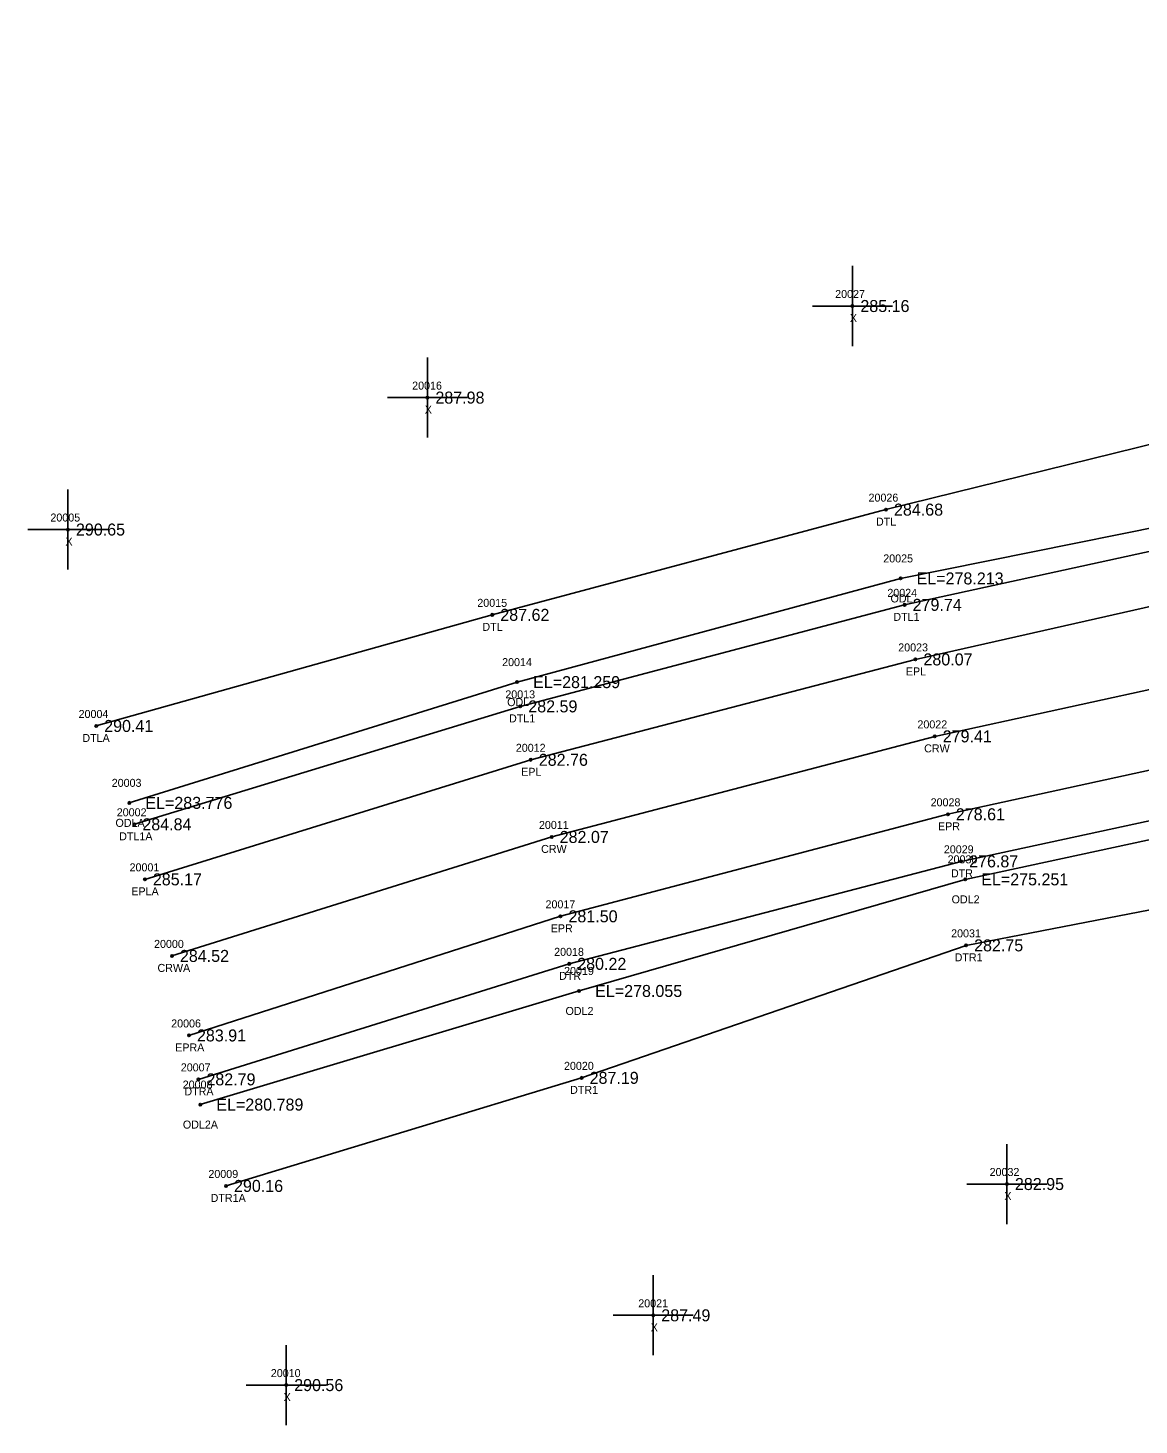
# Model space of a CAD drawing. Extents: x 2275563 to 2277161, y 1075719 to 1076412.
# Drawn here: x 2275563.1 to 2275701.9, y 1075902.3 to 1076077 of the extents above; entities that cross this region are included whole.
import ezdxf

# ---------------------------------------------------------------- set-up
doc = ezdxf.new("R2010")
doc.units = 0
for name, color, linetype in [('RD_DTM_BkLn1', 7, 'Continuous'), ('RD_EX_H2O', 7, 'Continuous'), ('RD_EX_H2O_txCode', 7, 'Continuous'), ('RD_EX_Misc', 7, 'Continuous'), ('RD_EX_Misc_txCode', 7, 'Continuous'), ('RD_EX_Road', 7, 'Continuous'), ('RD_EX_Road_txCode', 7, 'Continuous'), ('RD_EX_TX_H2O_ELEV', 7, 'Continuous'), ('RD_EX_TX_Misc_ELEV', 7, 'Continuous'), ('RD_EX_TX_Road_ELEV', 7, 'Continuous'), ('RD_HC_Survey_ELEV', 7, 'Continuous'), ('RD_HC_Survey_txCode', 7, 'Continuous'), ('RD_SMD_Locator', 7, 'Continuous')]:
    doc.layers.add(name, color=color, linetype=linetype)

msp = doc.modelspace()

# ---------------------------------------------------------------- linework, layer by layer
at = {"layer": 'RD_DTM_BkLn1'}
msp.add_lwpolyline([(2275581.11, 1075960.98), (2275628.56, 1075975.85), (2275676.42, 1075988.42), (2275723.3, 1075998.64), (2275773.11, 1076007.87), (2275820.75, 1076014.85), (2275866.6, 1076020.4), (2275966.91, 1076031.19), (2276055.16, 1076040.4), (2276149.88, 1076050.18), (2276235.38, 1076058.41), (2276319.71, 1076067.21)], dxfattribs=at)
at = {"layer": 'RD_EX_H2O'}
for points in [[(2275571.65, 1075989.72), (2275621.14, 1076003.61), (2275670.33, 1076016.76), (2275718.82, 1076028.73), (2275768.35, 1076037.39), (2275818.36, 1076043.83), (2275863.99, 1076048.58), (2275939.76, 1076056.32), (2275942.53, 1076068.3)], [(2275576.42, 1075977.43), (2275624.64, 1075992.17), (2275672.66, 1076004.86), (2275721.55, 1076015.52), (2275771.33, 1076024.61), (2275820.46, 1076031.17), (2275865.41, 1076036.37), (2275943.27, 1076044.07), (2275943.38, 1076052.27), (2275942.53, 1076068.3)], [(2275575.79, 1075980.11), (2275624.24, 1075995.2), (2275672.15, 1076008.16), (2275721.35, 1076018.05), (2275770.75, 1076027.72), (2275820.07, 1076033.88), (2275865.07, 1076039.19), (2275940.33, 1076048.37)], [(2275584.42, 1075945.55), (2275630.75, 1075959.99), (2275679.72, 1075972.8), (2275727.1, 1075983.01), (2275776.52, 1075992.46), (2275822.09, 1075998.61), (2275868.31, 1076005.5), (2275971.07, 1076013.85), (2276058.03, 1076018.84), (2276110, 1076025.4), (2276114.25, 1076022.31), (2276152.59, 1076021.64), (2276188.46, 1076022.22), (2276200.36, 1076021.35), (2276207.63, 1076015.4), (2276245.53, 1076014.24), (2276263.41, 1076017.81), (2276276.57, 1076007.97), (2276280.95, 1075989.03), (2276329.97, 1075967.39)], [(2275584.66, 1075942.4), (2275631.99, 1075956.6), (2275680.23, 1075970.55), (2275727.34, 1075980.71), (2275776.9, 1075989.93), (2275822.49, 1075996.83), (2275868.2, 1076003.14), (2275971.77, 1076011.3), (2276058.74, 1076015.62), (2276117.31, 1076020.2), (2276152.71, 1076018.31), (2276188.2, 1076020.3), (2276200.59, 1076018.25), (2276207.46, 1076011.88), (2276246.17, 1076010.02), (2276264.15, 1076012.48), (2276274.37, 1076006.56), (2276276.43, 1075986.9), (2276334.04, 1075961.68)], [(2275587.87, 1075932.23), (2275632.3, 1075945.74), (2275680.34, 1075962.3), (2275730.43, 1075971.98), (2275777.84, 1075981.49), (2275823.91, 1075987.34), (2275869.26, 1075992.75), (2275941.88, 1076000), (2275968.29, 1076005.71), (2275973.41, 1076009.09), (2276058.49, 1076013.63), (2276114.54, 1076018.47), (2276125.61, 1076012.99), (2276153.29, 1076014.06), (2276186.69, 1076017.67), (2276196.76, 1076016.05), (2276210.13, 1076008.45), (2276246.2, 1076005.42), (2276264.34, 1076010.6), (2276271.38, 1076006), (2276275.05, 1075983.37), (2276331.39, 1075956.06)]]:
    msp.add_lwpolyline(points, dxfattribs=at)
at = {"layer": 'RD_EX_Misc'}
for p, q in [((2275666.13, 1076037.21), (2275666.13, 1076047.21)), ((2275661.13, 1076042.21), (2275671.13, 1076042.21)), ((2275613.03, 1076025.76), (2275613.03, 1076035.76)), ((2275608.03, 1076030.76), (2275618.03, 1076030.76)), ((2275568.12, 1076009.27), (2275568.12, 1076019.27)), ((2275563.12, 1076014.27), (2275573.12, 1076014.27)), ((2275685.44, 1075927.47), (2275685.44, 1075937.47)), ((2275680.44, 1075932.47), (2275690.44, 1075932.47)), ((2275641.25, 1075911.06), (2275641.25, 1075921.06)), ((2275636.25, 1075916.06), (2275646.25, 1075916.06)), ((2275595.39, 1075902.34), (2275595.39, 1075912.34)), ((2275590.39, 1075907.34), (2275600.39, 1075907.34))]:
    msp.add_line(p, q, dxfattribs=at)
at = {"layer": 'RD_EX_Road'}
for points in [[(2275577.73, 1075970.55), (2275625.95, 1075985.49), (2275674.01, 1075998.04), (2275722.5, 1076008.98), (2275771.65, 1076017.82), (2275820.48, 1076025.1), (2275865.7, 1076030.61), (2275949.17, 1076039.36), (2275965.19, 1076041.07), (2276054.28, 1076050.49), (2276149.42, 1076060.39), (2276235.13, 1076068.68), (2276318.87, 1076076.96)], [(2275583.24, 1075951.04), (2275629.66, 1075965.93), (2275678.06, 1075978.68), (2275725.56, 1075989.06), (2275775.66, 1075998.23), (2275820.79, 1076005.15), (2275867.87, 1076010.76), (2275970.82, 1076021.78), (2276056.64, 1076030.61), (2276150.8, 1076040.39), (2276237.04, 1076048.76), (2276320.71, 1076057.95)]]:
    msp.add_lwpolyline(points, dxfattribs=at)
at = {"layer": 'RD_SMD_Locator'}
for centre in [(2275666.13, 1076042.21), (2275613.03, 1076030.76), (2275670.33, 1076016.76), (2275568.12, 1076014.27), (2275672.15, 1076008.16), (2275672.66, 1076004.86), (2275621.14, 1076003.61), (2275674.01, 1075998.04), (2275624.24, 1075995.2), (2275624.64, 1075992.17), (2275571.65, 1075989.72), (2275676.42, 1075988.42), (2275625.95, 1075985.49), (2275575.79, 1075980.11), (2275678.06, 1075978.68), (2275576.42, 1075977.43), (2275628.56, 1075975.85), (2275679.72, 1075972.8), (2275577.73, 1075970.55), (2275680.23, 1075970.55), (2275629.66, 1075965.93), (2275680.34, 1075962.3), (2275581.11, 1075960.98), (2275630.75, 1075959.99), (2275631.99, 1075956.6), (2275583.24, 1075951.04), (2275584.42, 1075945.55), (2275632.3, 1075945.74), (2275584.66, 1075942.4), (2275685.44, 1075932.47), (2275587.87, 1075932.23), (2275641.25, 1075916.06), (2275595.39, 1075907.34)]:
    msp.add_circle(centre, 0.15, dxfattribs=at)

# ---------------------------------------------------------------- texts
at = {"layer": 'RD_EX_H2O_txCode'}
for s, p in [('20026', (2275668.15, 1076017.76)), ('DTL', (2275669.08, 1076014.76)), ('20025', (2275669.99, 1076010.16)), ('20024', (2275670.5, 1076005.86)), ('ODL', (2275670.9, 1076005.16)), ('20015', (2275619.27, 1076004.61)), ('DTL', (2275619.9, 1076001.61)), ('DTL1', (2275671.25, 1076002.86)), ('20014', (2275622.37, 1075997.2)), ('20013', (2275622.77, 1075993.17)), ('ODL', (2275623, 1075992.2)), ('20004', (2275569.45, 1075990.72)), ('DTL1', (2275623.23, 1075990.17)), ('DTLA', (2275569.92, 1075987.72)), ('20003', (2275573.59, 1075982.11)), ('ODLA', (2275574.06, 1075977.11)), ('20002', (2275574.22, 1075978.43)), ('DTL1A', (2275574.52, 1075975.43)), ('20029', (2275677.56, 1075973.8)), ('20030', (2275678.03, 1075972.55)), ('DTR', (2275678.45, 1075970.8)), ('ODL2', (2275678.53, 1075967.55)), ('20031', (2275678.47, 1075963.3)), ('20018', (2275628.87, 1075960.99)), ('DTR1', (2275678.91, 1075960.3)), ('DTR', (2275629.48, 1075957.99)), ('20019', (2275630.11, 1075958.6)), ('ODL2', (2275630.29, 1075953.6)), ('20007', (2275582.22, 1075946.55)), ('20020', (2275630.1, 1075946.74)), ('20008', (2275582.46, 1075944.4)), ('DTRA', (2275582.67, 1075943.55)), ('DTR1', (2275630.86, 1075943.74)), ('ODL2A', (2275582.48, 1075939.4)), ('20009', (2275585.67, 1075933.23)), ('DTR1A', (2275585.95, 1075930.23))]:
    msp.add_text(s, height=1, dxfattribs=at).set_placement(p)
at = {"layer": 'RD_EX_Misc_txCode'}
for s, p in [('20027', (2275663.98, 1076043.21)), ('X', (2275665.82, 1076040.21)), ('20016', (2275611.13, 1076031.76)), ('X', (2275612.71, 1076028.76)), ('20005', (2275565.93, 1076015.27)), ('X', (2275567.81, 1076012.27)), ('20032', (2275683.28, 1075933.47)), ('X', (2275685.12, 1075930.47)), ('20021', (2275639.38, 1075917.06)), ('X', (2275640.94, 1075914.06)), ('20010', (2275593.47, 1075908.34)), ('X', (2275595.07, 1075905.34))]:
    msp.add_text(s, height=1, dxfattribs=at).set_placement(p)
at = {"layer": 'RD_EX_Road_txCode'}
for s, p in [('20023', (2275671.86, 1075999.04)), ('EPL', (2275672.81, 1075996.04)), ('20012', (2275624.08, 1075986.49)), ('EPL', (2275624.75, 1075983.49)), ('20028', (2275675.91, 1075979.68)), ('EPR', (2275676.83, 1075976.68)), ('20001', (2275575.82, 1075971.55)), ('EPLA', (2275576.04, 1075968.55)), ('20017', (2275627.79, 1075966.93)), ('EPR', (2275628.44, 1075963.93)), ('20006', (2275581.02, 1075952.04)), ('EPRA', (2275581.52, 1075949.04))]:
    msp.add_text(s, height=1, dxfattribs=at).set_placement(p)
at = {"layer": 'RD_EX_TX_H2O_ELEV'}
for s, p in [('284.68', (2275671.33, 1076016.01)), ('EL=278.213', (2275674.15, 1076007.41)), ('287.62', (2275622.14, 1076002.86)), ('279.74', (2275673.66, 1076004.11)), ('EL=281.259', (2275626.24, 1075994.45)), ('282.59', (2275625.64, 1075991.42)), ('290.41', (2275572.65, 1075988.97)), ('EL=283.776', (2275577.79, 1075979.36)), ('284.84', (2275577.42, 1075976.68)), ('276.87', (2275680.72, 1075972.05)), ('EL=275.251', (2275682.23, 1075969.8)), ('282.75', (2275681.34, 1075961.55)), ('280.22', (2275631.75, 1075959.24)), ('EL=278.055', (2275633.99, 1075955.85)), ('287.19', (2275633.3, 1075944.99)), ('282.79', (2275585.42, 1075944.8)), ('EL=280.789', (2275586.66, 1075941.65)), ('290.16', (2275588.87, 1075931.48))]:
    msp.add_text(s, height=1.5, dxfattribs=at).set_placement(p)
at = {"layer": 'RD_EX_TX_Misc_ELEV'}
for s, p in [('285.16', (2275667.13, 1076041.46)), ('287.98', (2275614.03, 1076030.01)), ('290.65', (2275569.12, 1076013.52)), ('282.95', (2275686.44, 1075931.72)), ('287.49', (2275642.25, 1075915.31)), ('290.56', (2275596.39, 1075906.59))]:
    msp.add_text(s, height=1.5, dxfattribs=at).set_placement(p)
at = {"layer": 'RD_EX_TX_Road_ELEV'}
for s, p in [('280.07', (2275675.01, 1075997.29)), ('282.76', (2275626.95, 1075984.74)), ('278.61', (2275679.06, 1075977.93)), ('285.17', (2275578.73, 1075969.8)), ('281.50', (2275630.66, 1075965.18)), ('283.91', (2275584.24, 1075950.29))]:
    msp.add_text(s, height=1.5, dxfattribs=at).set_placement(p)
at = {"layer": 'RD_HC_Survey_ELEV'}
for s, p in [('279.41', (2275677.42, 1075987.67)), ('282.07', (2275629.56, 1075975.1)), ('284.52', (2275582.11, 1075960.23))]:
    msp.add_text(s, height=1.5, dxfattribs=at).set_placement(p)
at = {"layer": 'RD_HC_Survey_txCode'}
for s, p in [('20022', (2275674.26, 1075989.42)), ('CRW', (2275675.1, 1075986.42)), ('20011', (2275626.97, 1075976.85)), ('CRW', (2275627.24, 1075973.85)), ('20000', (2275578.88, 1075961.98)), ('CRWA', (2275579.31, 1075958.98))]:
    msp.add_text(s, height=1, dxfattribs=at).set_placement(p)

doc.saveas('drawing.dxf')
